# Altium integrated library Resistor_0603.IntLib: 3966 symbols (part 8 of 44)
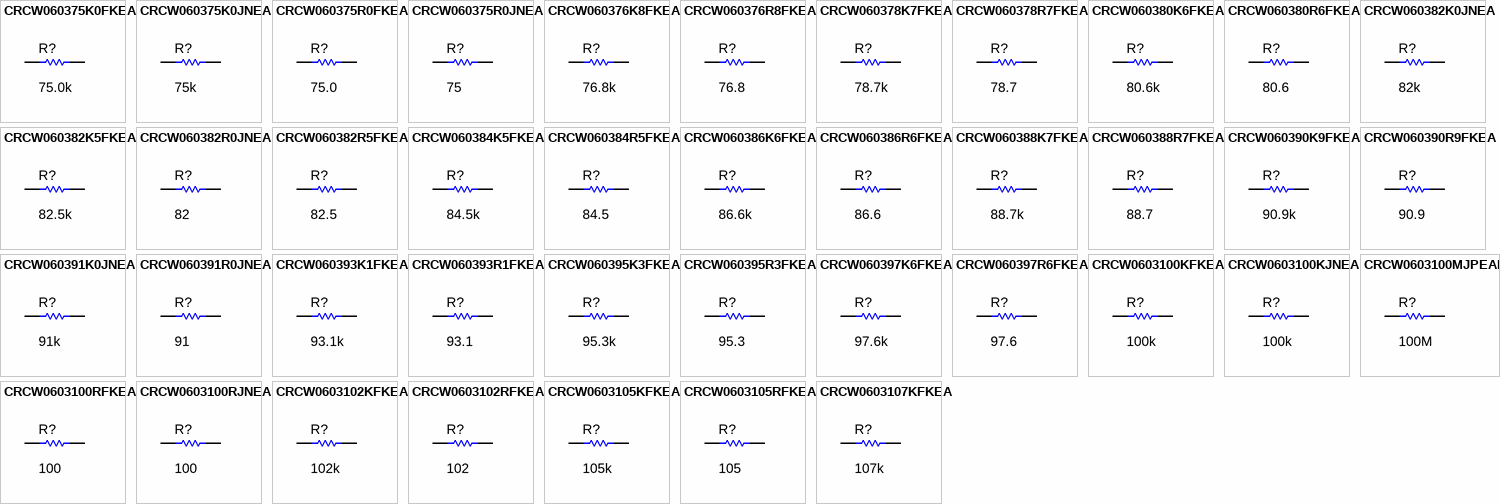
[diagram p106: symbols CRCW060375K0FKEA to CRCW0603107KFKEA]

## CRCW060395R3FKEA
designator R?  ValueDisplayed: 95.3  (hidden comment: CRCW060395R3FKEA)
RES, 95.3, 1%, 0.1 W, 0603; Manufacturer: Vishay-Dale; CompType: Resistor; Value: 95.3; Value_Code: 95R3; Tolerance_%: 1; Power_W: 0.1; Value2: 0.1W; VDC_V: 75; TempCo: 100 ppm/C; SizeArea_mm2: 1.28; SizeX_mm: 1.6; SizeY_mm: 0.8; EIA_Code: E96; U/M: EA; AEC Category: Q200
signal-integrity model Resistor
simulation model Resistor
footprint 0603
footprint 0603M
footprint 0603L
footprint 0603_HV
footprint 0603S
pins: 1, 2

## CRCW060397K6FKEA
designator R?  ValueDisplayed: 97.6k  (hidden comment: CRCW060397K6FKEA)
RES, 97.6 k, 1%, 0.1 W, 0603; Manufacturer: Vishay-Dale; CompType: Resistor; Value: 97.6k; Res_ohm: 97600; Value_Code: 97k6; Tolerance_%: 1; Power_W: 0.1; Value2: 0.1W; VDC_V: 75; TempCo: 100 ppm/C; SizeArea_mm2: 1.28; SizeX_mm: 1.6; SizeY_mm: 0.8; EIA_Code: E96; U/M: EA; AEC Category: Q200; Green_Lifecycle: Active; Green_REACh: Passed
signal-integrity model Resistor
simulation model Resistor
footprint 0603
footprint 0603M
footprint 0603L
footprint 0603_HV
footprint 0603S
pins: 1, 2

## CRCW060397R6FKEA
designator R?  ValueDisplayed: 97.6  (hidden comment: CRCW060397R6FKEA)
RES, 97.6, 1%, 0.1 W, 0603; Manufacturer: Vishay-Dale; CompType: Resistor; Value: 97.6; Value_Code: 97R6; Tolerance_%: 1; Power_W: 0.1; Value2: 0.1W; VDC_V: 75; TempCo: 100 ppm/C; SizeArea_mm2: 1.28; SizeX_mm: 1.6; SizeY_mm: 0.8; EIA_Code: E96; U/M: EA; AEC Category: Q200
signal-integrity model Resistor
simulation model Resistor
footprint 0603
footprint 0603M
footprint 0603L
footprint 0603_HV
footprint 0603S
pins: 1, 2

## CRCW0603100KFKEA
designator R?  ValueDisplayed: 100k  (hidden comment: CRCW0603100KFKEA)
RES, 100 k, 1%, 0.1 W, 0603; Manufacturer: Vishay-Dale; CompType: Resistor; Value: 100k; Res_ohm: 100000; Tolerance_%: 1; Power_W: 0.1; Value2: 0.1W; VDC_V: 75; TempCo: 100 ppm/C; SizeArea_mm2: 1.28; SizeX_mm: 1.6; SizeY_mm: 0.8; EIA_Code: E96; U/M: EA; AEC Category: Q200; Green_Lifecycle: Active; Green_REACh: Passed
signal-integrity model Resistor
simulation model Resistor
footprint 0603
footprint 0603M
footprint 0603L
footprint 0603_HV
footprint 0603S
pins: 1, 2

## CRCW0603100KJNEA
designator R?  ValueDisplayed: 100k  (hidden comment: CRCW0603100KJNEA)
RES, 100 k, 5%, 0.1 W, 0603; Manufacturer: Vishay-Dale; CompType: Resistor; Value: 100k; Res_ohm: 100000; Tolerance_%: 5; Power_W: 0.1; Value2: 0.1W; VDC_V: 75; TempCo: 200 ppm/C; SizeArea_mm2: 1.28; SizeX_mm: 1.6; SizeY_mm: 0.8; SizeZ_mm: 1; EIA_Code: E24; U/M: EA; AEC Category: Q200; Green_Lifecycle: Active; Green_REACh: Passed
signal-integrity model Resistor
simulation model Resistor
footprint 0603
footprint 0603M
footprint 0603L
footprint 0603_HV
footprint 0603S
pins: 1, 2

## CRCW0603100MJPEAHR
designator R?  ValueDisplayed: 100M  (hidden comment: CRCW0603100MJPEAHR)
RES, 100 M, 5%, 0.1 W, 0603; Manufacturer: Vishay-Dale; CompType: Resistor; Value: 100Meg; Res_ohm: 100000000; Tolerance_%: 5; Power_W: 0.1; Value2: 0.1W; VDC_V: 75; TempCo: 500 ppm/C; SizeArea_mm2: 1.28; SizeX_mm: 1.6; SizeY_mm: 0.8; SizeZ_mm: 1; U/M: EA; AEC Category: Q200
signal-integrity model Resistor
simulation model Resistor
footprint 0603
footprint 0603M
footprint 0603L
footprint 0603_HV
footprint 0603S
pins: 1, 2

## CRCW0603100RFKEA
designator R?  ValueDisplayed: 100  (hidden comment: CRCW0603100RFKEA)
RES, 100, 1%, 0.1 W, 0603; Manufacturer: Vishay-Dale; CompType: Resistor; Value: 100; Value_Code: 100R; Tolerance_%: 1; Power_W: 0.1; Value2: 0.1W; VDC_V: 75; TempCo: 100 ppm/C; SizeArea_mm2: 1.28; SizeX_mm: 1.6; SizeY_mm: 0.8; EIA_Code: E96; U/M: EA; AEC Category: Q200; Green_Lifecycle: Active; Green_REACh: Passed
signal-integrity model Resistor
simulation model Resistor
footprint 0603
footprint 0603M
footprint 0603L
footprint 0603_HV
footprint 0603S
pins: 1, 2

## CRCW0603100RJNEA
designator R?  ValueDisplayed: 100  (hidden comment: CRCW0603100RJNEA)
RES, 100, 5%, 0.1 W, 0603; Manufacturer: Vishay-Dale; CompType: Resistor; Value: 100; Value_Code: 100R; Tolerance_%: 5; Power_W: 0.1; Value2: 0.1W; VDC_V: 75; TempCo: 200 ppm/C; SizeArea_mm2: 1.28; SizeX_mm: 1.6; SizeY_mm: 0.8; SizeZ_mm: 1; EIA_Code: E24; U/M: EA; AEC Category: Q200; Green_Lifecycle: Active; Green_REACh: Passed
signal-integrity model Resistor
simulation model Resistor
footprint 0603
footprint 0603M
footprint 0603L
footprint 0603_HV
footprint 0603S
pins: 1, 2

## CRCW0603102KFKEA
designator R?  ValueDisplayed: 102k  (hidden comment: CRCW0603102KFKEA)
RES, 102 k, 1%, 0.1 W, 0603; Manufacturer: Vishay-Dale; CompType: Resistor; Value: 102k; Res_ohm: 102000; Tolerance_%: 1; Power_W: 0.1; Value2: 0.1W; VDC_V: 75; TempCo: 100 ppm/C; SizeArea_mm2: 1.28; SizeX_mm: 1.6; SizeY_mm: 0.8; EIA_Code: E96; U/M: EA; AEC Category: Q200; Green_Lifecycle: Active; Green_REACh: Passed
signal-integrity model Resistor
simulation model Resistor
footprint 0603
footprint 0603M
footprint 0603L
footprint 0603_HV
footprint 0603S
pins: 1, 2

## CRCW0603102RFKEA
designator R?  ValueDisplayed: 102  (hidden comment: CRCW0603102RFKEA)
RES, 102, 1%, 0.1 W, 0603; Manufacturer: Vishay-Dale; CompType: Resistor; Value: 102; Value_Code: 102R; Tolerance_%: 1; Power_W: 0.1; Value2: 0.1W; VDC_V: 75; TempCo: 100 ppm/C; SizeArea_mm2: 1.28; SizeX_mm: 1.6; SizeY_mm: 0.8; EIA_Code: E96; U/M: EA; AEC Category: Q200
signal-integrity model Resistor
simulation model Resistor
footprint 0603
footprint 0603M
footprint 0603L
footprint 0603_HV
footprint 0603S
pins: 1, 2

## CRCW0603105KFKEA
designator R?  ValueDisplayed: 105k  (hidden comment: CRCW0603105KFKEA)
RES, 105 k, 1%, 0.1 W, 0603; Manufacturer: Vishay-Dale; CompType: Resistor; Value: 105k; Res_ohm: 105000; Tolerance_%: 1; Power_W: 0.1; Value2: 0.1W; VDC_V: 75; TempCo: 100 ppm/C; SizeArea_mm2: 1.28; SizeX_mm: 1.6; SizeY_mm: 0.8; EIA_Code: E96; U/M: EA; AEC Category: Q200; Green_Lifecycle: Active; Green_REACh: Passed
signal-integrity model Resistor
simulation model Resistor
footprint 0603
footprint 0603M
footprint 0603L
footprint 0603_HV
footprint 0603S
pins: 1, 2

## CRCW0603105RFKEA
designator R?  ValueDisplayed: 105  (hidden comment: CRCW0603105RFKEA)
RES, 105, 1%, 0.1 W, 0603; Manufacturer: Vishay-Dale; CompType: Resistor; Value: 105; Value_Code: 105R; Tolerance_%: 1; Power_W: 0.1; Value2: 0.1W; VDC_V: 75; TempCo: 100 ppm/C; SizeArea_mm2: 1.28; SizeX_mm: 1.6; SizeY_mm: 0.8; EIA_Code: E96; U/M: EA; AEC Category: Q200
signal-integrity model Resistor
simulation model Resistor
footprint 0603
footprint 0603M
footprint 0603L
footprint 0603_HV
footprint 0603S
pins: 1, 2

## CRCW0603107KFKEA
designator R?  ValueDisplayed: 107k  (hidden comment: CRCW0603107KFKEA)
RES, 107 k, 1%, 0.1 W, 0603; Manufacturer: Vishay-Dale; CompType: Resistor; Value: 107k; Res_ohm: 107000; Tolerance_%: 1; Power_W: 0.1; Value2: 0.1W; VDC_V: 75; TempCo: 100 ppm/C; SizeArea_mm2: 1.28; SizeX_mm: 1.6; SizeY_mm: 0.8; EIA_Code: E96; U/M: EA; AEC Category: Q200
signal-integrity model Resistor
simulation model Resistor
footprint 0603
footprint 0603M
footprint 0603L
footprint 0603_HV
footprint 0603S
pins: 1, 2

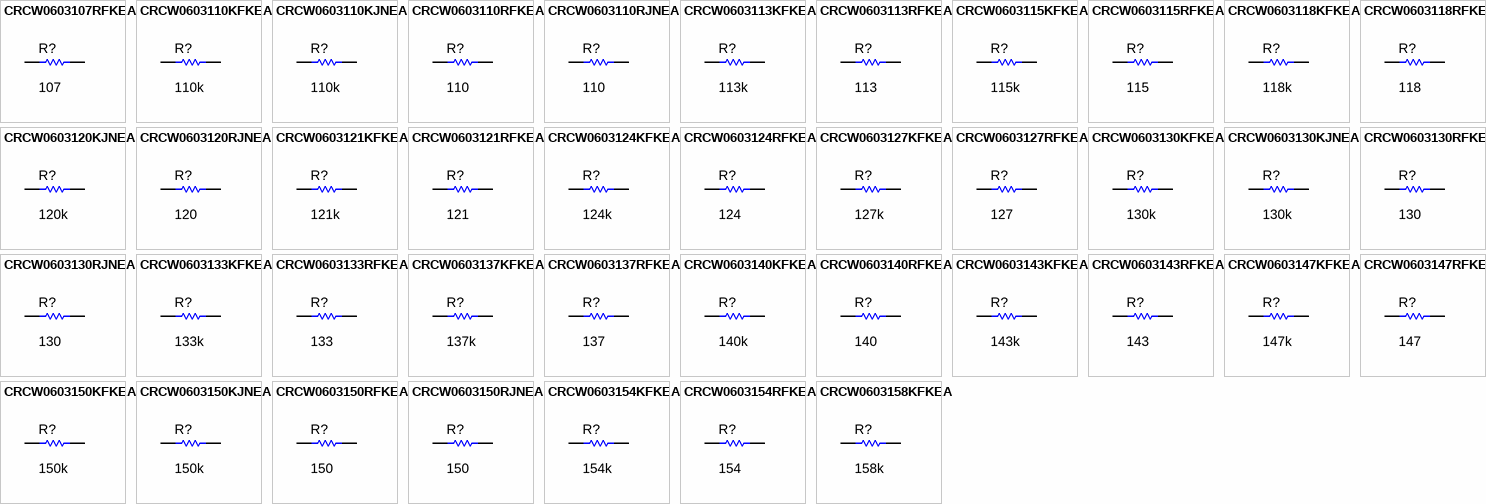
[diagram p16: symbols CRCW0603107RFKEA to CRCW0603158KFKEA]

## CRCW0603107RFKEA
designator R?  ValueDisplayed: 107  (hidden comment: CRCW0603107RFKEA)
RES, 107, 1%, 0.1 W, 0603; Manufacturer: Vishay-Dale; CompType: Resistor; Value: 107; Value_Code: 107R; Tolerance_%: 1; Power_W: 0.1; Value2: 0.1W; VDC_V: 75; TempCo: 100 ppm/C; SizeArea_mm2: 1.28; SizeX_mm: 1.6; SizeY_mm: 0.8; EIA_Code: E96; U/M: EA; AEC Category: Q200
signal-integrity model Resistor
simulation model Resistor
footprint 0603
footprint 0603M
footprint 0603L
footprint 0603_HV
footprint 0603S
pins: 1, 2

## CRCW0603110KFKEA
designator R?  ValueDisplayed: 110k  (hidden comment: CRCW0603110KFKEA)
RES, 110 k, 1%, 0.1 W, 0603; Manufacturer: Vishay-Dale; CompType: Resistor; Value: 110k; Res_ohm: 110000; Tolerance_%: 1; Power_W: 0.1; Value2: 0.1W; VDC_V: 75; TempCo: 100 ppm/C; SizeArea_mm2: 1.28; SizeX_mm: 1.6; SizeY_mm: 0.8; EIA_Code: E96; U/M: EA; AEC Category: Q200; Green_Lifecycle: Active; Green_REACh: Passed
signal-integrity model Resistor
simulation model Resistor
footprint 0603
footprint 0603M
footprint 0603L
footprint 0603_HV
footprint 0603S
pins: 1, 2

## CRCW0603110KJNEA
designator R?  ValueDisplayed: 110k  (hidden comment: CRCW0603110KJNEA)
RES, 110 k, 5%, 0.1 W, 0603; Manufacturer: Vishay-Dale; CompType: Resistor; Value: 110k; Res_ohm: 110000; Tolerance_%: 5; Power_W: 0.1; Value2: 0.1W; VDC_V: 75; TempCo: 200 ppm/C; SizeArea_mm2: 1.28; SizeX_mm: 1.6; SizeY_mm: 0.8; SizeZ_mm: 1; EIA_Code: E24; U/M: EA; AEC Category: Q200
signal-integrity model Resistor
simulation model Resistor
footprint 0603
footprint 0603M
footprint 0603L
footprint 0603_HV
footprint 0603S
pins: 1, 2

## CRCW0603110RFKEA
designator R?  ValueDisplayed: 110  (hidden comment: CRCW0603110RFKEA)
RES, 110, 1%, 0.1 W, 0603; Manufacturer: Vishay-Dale; CompType: Resistor; Value: 110; Value_Code: 110R; Tolerance_%: 1; Power_W: 0.1; Value2: 0.1W; VDC_V: 75; TempCo: 100 ppm/C; SizeArea_mm2: 1.28; SizeX_mm: 1.6; SizeY_mm: 0.8; EIA_Code: E96; U/M: EA; AEC Category: Q200
signal-integrity model Resistor
simulation model Resistor
footprint 0603
footprint 0603M
footprint 0603L
footprint 0603_HV
footprint 0603S
pins: 1, 2

## CRCW0603110RJNEA
designator R?  ValueDisplayed: 110  (hidden comment: CRCW0603110RJNEA)
RES, 110, 5%, 0.1 W, 0603; Manufacturer: Vishay-Dale; CompType: Resistor; Value: 110; Value_Code: 110R; Tolerance_%: 5; Power_W: 0.1; Value2: 0.1W; VDC_V: 75; TempCo: 200 ppm/C; SizeArea_mm2: 1.28; SizeX_mm: 1.6; SizeY_mm: 0.8; SizeZ_mm: 1; EIA_Code: E24; U/M: EA; AEC Category: Q200
signal-integrity model Resistor
simulation model Resistor
footprint 0603
footprint 0603M
footprint 0603L
footprint 0603_HV
footprint 0603S
pins: 1, 2

## CRCW0603113KFKEA
designator R?  ValueDisplayed: 113k  (hidden comment: CRCW0603113KFKEA)
RES, 113 k, 1%, 0.1 W, 0603; Manufacturer: Vishay-Dale; CompType: Resistor; Value: 113k; Res_ohm: 113000; Tolerance_%: 1; Power_W: 0.1; Value2: 0.1W; VDC_V: 75; TempCo: 100 ppm/C; SizeArea_mm2: 1.28; SizeX_mm: 1.6; SizeY_mm: 0.8; EIA_Code: E96; U/M: EA; AEC Category: Q200; Green_Lifecycle: Active; Green_REACh: Passed
signal-integrity model Resistor
simulation model Resistor
footprint 0603
footprint 0603M
footprint 0603L
footprint 0603_HV
footprint 0603S
pins: 1, 2

## CRCW0603113RFKEA
designator R?  ValueDisplayed: 113  (hidden comment: CRCW0603113RFKEA)
RES, 113, 1%, 0.1 W, 0603; Manufacturer: Vishay-Dale; CompType: Resistor; Value: 113; Value_Code: 113R; Tolerance_%: 1; Power_W: 0.1; Value2: 0.1W; VDC_V: 75; TempCo: 100 ppm/C; SizeArea_mm2: 1.28; SizeX_mm: 1.6; SizeY_mm: 0.8; EIA_Code: E96; U/M: EA; AEC Category: Q200; Green_Lifecycle: Active; Green_REACh: Passed
signal-integrity model Resistor
simulation model Resistor
footprint 0603
footprint 0603M
footprint 0603L
footprint 0603_HV
footprint 0603S
pins: 1, 2

## CRCW0603115KFKEA
designator R?  ValueDisplayed: 115k  (hidden comment: CRCW0603115KFKEA)
RES, 115 k, 1%, 0.1 W, 0603; Manufacturer: Vishay-Dale; CompType: Resistor; Value: 115k; Res_ohm: 115000; Tolerance_%: 1; Power_W: 0.1; Value2: 0.1W; VDC_V: 75; TempCo: 100 ppm/C; SizeArea_mm2: 1.28; SizeX_mm: 1.6; SizeY_mm: 0.8; EIA_Code: E96; U/M: EA; AEC Category: Q200; Green_Lifecycle: Active; Green_REACh: Passed
signal-integrity model Resistor
simulation model Resistor
footprint 0603
footprint 0603M
footprint 0603L
footprint 0603_HV
footprint 0603S
pins: 1, 2

## CRCW0603115RFKEA
designator R?  ValueDisplayed: 115  (hidden comment: CRCW0603115RFKEA)
RES, 115, 1%, 0.1 W, 0603; Manufacturer: Vishay-Dale; CompType: Resistor; Value: 115; Value_Code: 115R; Tolerance_%: 1; Power_W: 0.1; Value2: 0.1W; VDC_V: 75; TempCo: 100 ppm/C; SizeArea_mm2: 1.28; SizeX_mm: 1.6; SizeY_mm: 0.8; EIA_Code: E96; U/M: EA; AEC Category: Q200
signal-integrity model Resistor
simulation model Resistor
footprint 0603
footprint 0603M
footprint 0603L
footprint 0603_HV
footprint 0603S
pins: 1, 2

## CRCW0603118KFKEA
designator R?  ValueDisplayed: 118k  (hidden comment: CRCW0603118KFKEA)
RES, 118 k, 1%, 0.1 W, 0603; Manufacturer: Vishay-Dale; CompType: Resistor; Value: 118k; Res_ohm: 118000; Tolerance_%: 1; Power_W: 0.1; Value2: 0.1W; VDC_V: 75; TempCo: 100 ppm/C; SizeArea_mm2: 1.28; SizeX_mm: 1.6; SizeY_mm: 0.8; EIA_Code: E96; U/M: EA; AEC Category: Q200; Green_Lifecycle: Active; Green_REACh: Passed
signal-integrity model Resistor
simulation model Resistor
footprint 0603
footprint 0603M
footprint 0603L
footprint 0603_HV
footprint 0603S
pins: 1, 2

## CRCW0603118RFKEA
designator R?  ValueDisplayed: 118  (hidden comment: CRCW0603118RFKEA)
RES, 118, 1%, 0.1 W, 0603; Manufacturer: Vishay-Dale; CompType: Resistor; Value: 118; Value_Code: 118R; Tolerance_%: 1; Power_W: 0.1; Value2: 0.1W; VDC_V: 75; TempCo: 100 ppm/C; SizeArea_mm2: 1.28; SizeX_mm: 1.6; SizeY_mm: 0.8; EIA_Code: E96; U/M: EA; AEC Category: Q200
signal-integrity model Resistor
simulation model Resistor
footprint 0603
footprint 0603M
footprint 0603L
footprint 0603_HV
footprint 0603S
pins: 1, 2

## CRCW0603120KJNEA
designator R?  ValueDisplayed: 120k  (hidden comment: CRCW0603120KJNEA)
RES, 120 k, 5%, 0.1 W, 0603; Manufacturer: Vishay-Dale; CompType: Resistor; Value: 120k; Res_ohm: 120000; Tolerance_%: 5; Power_W: 0.1; Value2: 0.1W; VDC_V: 75; TempCo: 200 ppm/C; SizeArea_mm2: 1.28; SizeX_mm: 1.6; SizeY_mm: 0.8; SizeZ_mm: 1; EIA_Code: E24; U/M: EA; AEC Category: Q200
signal-integrity model Resistor
simulation model Resistor
footprint 0603
footprint 0603M
footprint 0603L
footprint 0603_HV
footprint 0603S
pins: 1, 2

## CRCW0603120RJNEA
designator R?  ValueDisplayed: 120  (hidden comment: CRCW0603120RJNEA)
RES, 120, 5%, 0.1 W, 0603; Manufacturer: Vishay-Dale; CompType: Resistor; Value: 120; Value_Code: 120R; Tolerance_%: 5; Power_W: 0.1; Value2: 0.1W; VDC_V: 75; TempCo: 200 ppm/C; SizeArea_mm2: 1.28; SizeX_mm: 1.6; SizeY_mm: 0.8; SizeZ_mm: 1; EIA_Code: E24; U/M: EA; AEC Category: Q200; Green_Lifecycle: Active; Green_REACh: Passed
signal-integrity model Resistor
simulation model Resistor
footprint 0603
footprint 0603M
footprint 0603L
footprint 0603_HV
footprint 0603S
pins: 1, 2

## CRCW0603121KFKEA
designator R?  ValueDisplayed: 121k  (hidden comment: CRCW0603121KFKEA)
RES, 121 k, 1%, 0.1 W, 0603; Manufacturer: Vishay-Dale; CompType: Resistor; Value: 121k; Res_ohm: 121000; Tolerance_%: 1; Power_W: 0.1; Value2: 0.1W; VDC_V: 75; TempCo: 100 ppm/C; SizeArea_mm2: 1.28; SizeX_mm: 1.6; SizeY_mm: 0.8; EIA_Code: E96; U/M: EA; AEC Category: Q200; Green_Lifecycle: Active; Green_REACh: Passed
signal-integrity model Resistor
simulation model Resistor
footprint 0603
footprint 0603M
footprint 0603L
footprint 0603_HV
footprint 0603S
pins: 1, 2

## CRCW0603121RFKEA
designator R?  ValueDisplayed: 121  (hidden comment: CRCW0603121RFKEA)
RES, 121, 1%, 0.1 W, 0603; Manufacturer: Vishay-Dale; CompType: Resistor; Value: 121; Value_Code: 121R; Tolerance_%: 1; Power_W: 0.1; Value2: 0.1W; VDC_V: 75; TempCo: 100 ppm/C; SizeArea_mm2: 1.28; SizeX_mm: 1.6; SizeY_mm: 0.8; EIA_Code: E96; U/M: EA; AEC Category: Q200
signal-integrity model Resistor
simulation model Resistor
footprint 0603
footprint 0603M
footprint 0603L
footprint 0603_HV
footprint 0603S
pins: 1, 2

## CRCW0603124KFKEA
designator R?  ValueDisplayed: 124k  (hidden comment: CRCW0603124KFKEA)
RES, 124 k, 1%, 0.1 W, 0603; Manufacturer: Vishay-Dale; CompType: Resistor; Value: 124k; Res_ohm: 124000; Tolerance_%: 1; Power_W: 0.1; Value2: 0.1W; VDC_V: 75; TempCo: 100 ppm/C; SizeArea_mm2: 1.28; SizeX_mm: 1.6; SizeY_mm: 0.8; EIA_Code: E96; U/M: EA; AEC Category: Q200; Green_Lifecycle: Active; Green_REACh: Passed
signal-integrity model Resistor
simulation model Resistor
footprint 0603
footprint 0603M
footprint 0603L
footprint 0603_HV
footprint 0603S
pins: 1, 2

## CRCW0603124RFKEA
designator R?  ValueDisplayed: 124  (hidden comment: CRCW0603124RFKEA)
RES, 124, 1%, 0.1 W, 0603; Manufacturer: Vishay-Dale; CompType: Resistor; Value: 124; Value_Code: 124R; Tolerance_%: 1; Power_W: 0.1; Value2: 0.1W; VDC_V: 75; TempCo: 100 ppm/C; SizeArea_mm2: 1.28; SizeX_mm: 1.6; SizeY_mm: 0.8; EIA_Code: E96; U/M: EA; AEC Category: Q200
signal-integrity model Resistor
simulation model Resistor
footprint 0603
footprint 0603M
footprint 0603L
footprint 0603_HV
footprint 0603S
pins: 1, 2

## CRCW0603127KFKEA
designator R?  ValueDisplayed: 127k  (hidden comment: CRCW0603127KFKEA)
RES, 127 k, 1%, 0.1 W, 0603; Manufacturer: Vishay-Dale; CompType: Resistor; Value: 127k; Res_ohm: 127000; Tolerance_%: 1; Power_W: 0.1; Value2: 0.1W; VDC_V: 75; TempCo: 100 ppm/C; SizeArea_mm2: 1.28; SizeX_mm: 1.6; SizeY_mm: 0.8; EIA_Code: E96; U/M: EA; AEC Category: Q200; Green_Lifecycle: Active; Green_REACh: Passed
signal-integrity model Resistor
simulation model Resistor
footprint 0603
footprint 0603M
footprint 0603L
footprint 0603_HV
footprint 0603S
pins: 1, 2

## CRCW0603127RFKEA
designator R?  ValueDisplayed: 127  (hidden comment: CRCW0603127RFKEA)
RES, 127, 1%, 0.1 W, 0603; Manufacturer: Vishay-Dale; CompType: Resistor; Value: 127; Value_Code: 127R; Tolerance_%: 1; Power_W: 0.1; Value2: 0.1W; VDC_V: 75; TempCo: 100 ppm/C; SizeArea_mm2: 1.28; SizeX_mm: 1.6; SizeY_mm: 0.8; EIA_Code: E96; U/M: EA; AEC Category: Q200
signal-integrity model Resistor
simulation model Resistor
footprint 0603
footprint 0603M
footprint 0603L
footprint 0603_HV
footprint 0603S
pins: 1, 2

## CRCW0603130KFKEA
designator R?  ValueDisplayed: 130k  (hidden comment: CRCW0603130KFKEA)
RES, 130 k, 1%, 0.1 W, 0603; Manufacturer: Vishay-Dale; CompType: Resistor; Value: 130k; Res_ohm: 130000; Tolerance_%: 1; Power_W: 0.1; Value2: 0.1W; VDC_V: 75; TempCo: 100 ppm/C; SizeArea_mm2: 1.28; SizeX_mm: 1.6; SizeY_mm: 0.8; EIA_Code: E96; U/M: EA; AEC Category: Q200; Green_Lifecycle: Active; Green_REACh: Passed
signal-integrity model Resistor
simulation model Resistor
footprint 0603
footprint 0603M
footprint 0603L
footprint 0603_HV
footprint 0603S
pins: 1, 2

## CRCW0603130KJNEA
designator R?  ValueDisplayed: 130k  (hidden comment: CRCW0603130KJNEA)
RES, 130 k, 5%, 0.1 W, 0603; Manufacturer: Vishay-Dale; CompType: Resistor; Value: 130k; Res_ohm: 130000; Tolerance_%: 5; Power_W: 0.1; Value2: 0.1W; VDC_V: 75; TempCo: 200 ppm/C; SizeArea_mm2: 1.28; SizeX_mm: 1.6; SizeY_mm: 0.8; SizeZ_mm: 1; EIA_Code: E24; U/M: EA; AEC Category: Q200; Green_Lifecycle: Active; Green_REACh: Passed
signal-integrity model Resistor
simulation model Resistor
footprint 0603
footprint 0603M
footprint 0603L
footprint 0603_HV
footprint 0603S
pins: 1, 2

## CRCW0603130RFKEA
designator R?  ValueDisplayed: 130  (hidden comment: CRCW0603130RFKEA)
RES, 130, 1%, 0.1 W, 0603; Manufacturer: Vishay-Dale; CompType: Resistor; Value: 130; Value_Code: 130R; Tolerance_%: 1; Power_W: 0.1; Value2: 0.1W; VDC_V: 75; TempCo: 100 ppm/C; SizeArea_mm2: 1.28; SizeX_mm: 1.6; SizeY_mm: 0.8; EIA_Code: E96; U/M: EA; AEC Category: Q200
signal-integrity model Resistor
simulation model Resistor
footprint 0603
footprint 0603M
footprint 0603L
footprint 0603_HV
footprint 0603S
pins: 1, 2

## CRCW0603130RJNEA
designator R?  ValueDisplayed: 130  (hidden comment: CRCW0603130RJNEA)
RES, 130, 5%, 0.1 W, 0603; Manufacturer: Vishay-Dale; CompType: Resistor; Value: 130; Value_Code: 130R; Tolerance_%: 5; Power_W: 0.1; Value2: 0.1W; VDC_V: 75; TempCo: 200 ppm/C; SizeArea_mm2: 1.28; SizeX_mm: 1.6; SizeY_mm: 0.8; SizeZ_mm: 1; EIA_Code: E24; U/M: EA; AEC Category: Q200
signal-integrity model Resistor
simulation model Resistor
footprint 0603
footprint 0603M
footprint 0603L
footprint 0603_HV
footprint 0603S
pins: 1, 2

## CRCW0603133KFKEA
designator R?  ValueDisplayed: 133k  (hidden comment: CRCW0603133KFKEA)
RES, 133 k, 1%, 0.1 W, 0603; Manufacturer: Vishay-Dale; CompType: Resistor; Value: 133k; Res_ohm: 133000; Tolerance_%: 1; Power_W: 0.1; Value2: 0.1W; VDC_V: 75; TempCo: 100 ppm/C; SizeArea_mm2: 1.28; SizeX_mm: 1.6; SizeY_mm: 0.8; EIA_Code: E96; U/M: EA; AEC Category: Q200; Green_Lifecycle: Active; Green_REACh: Passed
signal-integrity model Resistor
simulation model Resistor
footprint 0603
footprint 0603M
footprint 0603L
footprint 0603_HV
footprint 0603S
pins: 1, 2

## CRCW0603133RFKEA
designator R?  ValueDisplayed: 133  (hidden comment: CRCW0603133RFKEA)
RES, 133, 1%, 0.1 W, 0603; Manufacturer: Vishay-Dale; CompType: Resistor; Value: 133; Value_Code: 133R; Tolerance_%: 1; Power_W: 0.1; Value2: 0.1W; VDC_V: 75; TempCo: 100 ppm/C; SizeArea_mm2: 1.28; SizeX_mm: 1.6; SizeY_mm: 0.8; EIA_Code: E96; U/M: EA; AEC Category: Q200
signal-integrity model Resistor
simulation model Resistor
footprint 0603
footprint 0603M
footprint 0603L
footprint 0603_HV
footprint 0603S
pins: 1, 2

## CRCW0603137KFKEA
designator R?  ValueDisplayed: 137k  (hidden comment: CRCW0603137KFKEA)
RES, 137 k, 1%, 0.1 W, 0603; Manufacturer: Vishay-Dale; CompType: Resistor; Value: 137k; Res_ohm: 137000; Tolerance_%: 1; Power_W: 0.1; Value2: 0.1W; VDC_V: 75; TempCo: 100 ppm/C; SizeArea_mm2: 1.28; SizeX_mm: 1.6; SizeY_mm: 0.8; EIA_Code: E96; U/M: EA; AEC Category: Q200; Green_Lifecycle: Active; Green_REACh: Passed
signal-integrity model Resistor
simulation model Resistor
footprint 0603
footprint 0603M
footprint 0603L
footprint 0603_HV
footprint 0603S
pins: 1, 2

## CRCW0603137RFKEA
designator R?  ValueDisplayed: 137  (hidden comment: CRCW0603137RFKEA)
RES, 137, 1%, 0.1 W, 0603; Manufacturer: Vishay-Dale; CompType: Resistor; Value: 137; Value_Code: 137R; Tolerance_%: 1; Power_W: 0.1; Value2: 0.1W; VDC_V: 75; TempCo: 100 ppm/C; SizeArea_mm2: 1.28; SizeX_mm: 1.6; SizeY_mm: 0.8; EIA_Code: E96; U/M: EA; AEC Category: Q200; Green_Lifecycle: Active; Green_REACh: Passed
signal-integrity model Resistor
simulation model Resistor
footprint 0603
footprint 0603M
footprint 0603L
footprint 0603_HV
footprint 0603S
pins: 1, 2

## CRCW0603140KFKEA
designator R?  ValueDisplayed: 140k  (hidden comment: CRCW0603140KFKEA)
RES, 140 k, 1%, 0.1 W, 0603; Manufacturer: Vishay-Dale; CompType: Resistor; Value: 140k; Res_ohm: 140000; Tolerance_%: 1; Power_W: 0.1; Value2: 0.1W; VDC_V: 75; TempCo: 100 ppm/C; SizeArea_mm2: 1.28; SizeX_mm: 1.6; SizeY_mm: 0.8; EIA_Code: E96; U/M: EA; AEC Category: Q200; Green_Lifecycle: Active; Green_REACh: Passed
signal-integrity model Resistor
simulation model Resistor
footprint 0603
footprint 0603M
footprint 0603L
footprint 0603_HV
footprint 0603S
pins: 1, 2

## CRCW0603140RFKEA
designator R?  ValueDisplayed: 140  (hidden comment: CRCW0603140RFKEA)
RES, 140, 1%, 0.1 W, 0603; Manufacturer: Vishay-Dale; CompType: Resistor; Value: 140; Value_Code: 140R; Tolerance_%: 1; Power_W: 0.1; Value2: 0.1W; VDC_V: 75; TempCo: 100 ppm/C; SizeArea_mm2: 1.28; SizeX_mm: 1.6; SizeY_mm: 0.8; EIA_Code: E96; U/M: EA; AEC Category: Q200
signal-integrity model Resistor
simulation model Resistor
footprint 0603
footprint 0603M
footprint 0603L
footprint 0603_HV
footprint 0603S
pins: 1, 2

## CRCW0603143KFKEA
designator R?  ValueDisplayed: 143k  (hidden comment: CRCW0603143KFKEA)
RES, 143 k, 1%, 0.1 W, 0603; Manufacturer: Vishay-Dale; CompType: Resistor; Value: 143k; Res_ohm: 143000; Tolerance_%: 1; Power_W: 0.1; Value2: 0.1W; VDC_V: 75; TempCo: 100 ppm/C; SizeArea_mm2: 1.28; SizeX_mm: 1.6; SizeY_mm: 0.8; EIA_Code: E96; U/M: EA; AEC Category: Q200; Green_Lifecycle: Active; Green_REACh: Passed
signal-integrity model Resistor
simulation model Resistor
footprint 0603
footprint 0603M
footprint 0603L
footprint 0603_HV
footprint 0603S
pins: 1, 2

## CRCW0603143RFKEA
designator R?  ValueDisplayed: 143  (hidden comment: CRCW0603143RFKEA)
RES, 143, 1%, 0.1 W, 0603; Manufacturer: Vishay-Dale; CompType: Resistor; Value: 143; Value_Code: 143R; Tolerance_%: 1; Power_W: 0.1; Value2: 0.1W; VDC_V: 75; TempCo: 100 ppm/C; SizeArea_mm2: 1.28; SizeX_mm: 1.6; SizeY_mm: 0.8; EIA_Code: E96; U/M: EA; AEC Category: Q200; Green_Lifecycle: Active; Green_REACh: Passed
signal-integrity model Resistor
simulation model Resistor
footprint 0603
footprint 0603M
footprint 0603L
footprint 0603_HV
footprint 0603S
pins: 1, 2

## CRCW0603147KFKEA
designator R?  ValueDisplayed: 147k  (hidden comment: CRCW0603147KFKEA)
RES, 147 k, 1%, 0.1 W, 0603; Manufacturer: Vishay-Dale; CompType: Resistor; Value: 147k; Res_ohm: 147000; Tolerance_%: 1; Power_W: 0.1; Value2: 0.1W; VDC_V: 75; TempCo: 100 ppm/C; SizeArea_mm2: 1.28; SizeX_mm: 1.6; SizeY_mm: 0.8; EIA_Code: E96; U/M: EA; AEC Category: Q200; Green_Lifecycle: Active; Green_REACh: Passed
signal-integrity model Resistor
simulation model Resistor
footprint 0603
footprint 0603M
footprint 0603L
footprint 0603_HV
footprint 0603S
pins: 1, 2

## CRCW0603147RFKEA
designator R?  ValueDisplayed: 147  (hidden comment: CRCW0603147RFKEA)
RES, 147, 1%, 0.1 W, 0603; Manufacturer: Vishay-Dale; CompType: Resistor; Value: 147; Value_Code: 147R; Tolerance_%: 1; Power_W: 0.1; Value2: 0.1W; VDC_V: 75; TempCo: 100 ppm/C; SizeArea_mm2: 1.28; SizeX_mm: 1.6; SizeY_mm: 0.8; EIA_Code: E96; U/M: EA; AEC Category: Q200
signal-integrity model Resistor
simulation model Resistor
footprint 0603
footprint 0603M
footprint 0603L
footprint 0603_HV
footprint 0603S
pins: 1, 2

## CRCW0603150KFKEA
designator R?  ValueDisplayed: 150k  (hidden comment: CRCW0603150KFKEA)
RES, 150 k, 1%, 0.1 W, 0603; Manufacturer: Vishay-Dale; CompType: Resistor; Value: 150k; Res_ohm: 150000; Tolerance_%: 1; Power_W: 0.1; Value2: 0.1W; VDC_V: 75; TempCo: 100 ppm/C; SizeArea_mm2: 1.28; SizeX_mm: 1.6; SizeY_mm: 0.8; EIA_Code: E96; U/M: EA; AEC Category: Q200; Green_Lifecycle: Active; Green_REACh: Passed
signal-integrity model Resistor
simulation model Resistor
footprint 0603
footprint 0603M
footprint 0603L
footprint 0603_HV
footprint 0603S
pins: 1, 2

## CRCW0603150KJNEA
designator R?  ValueDisplayed: 150k  (hidden comment: CRCW0603150KJNEA)
RES, 150 k, 5%, 0.1 W, 0603; Manufacturer: Vishay-Dale; CompType: Resistor; Value: 150k; Res_ohm: 150000; Tolerance_%: 5; Power_W: 0.1; Value2: 0.1W; VDC_V: 75; TempCo: 200 ppm/C; SizeArea_mm2: 1.28; SizeX_mm: 1.6; SizeY_mm: 0.8; SizeZ_mm: 1; EIA_Code: E24; U/M: EA; AEC Category: Q200
signal-integrity model Resistor
simulation model Resistor
footprint 0603
footprint 0603M
footprint 0603L
footprint 0603_HV
footprint 0603S
pins: 1, 2

## CRCW0603150RFKEA
designator R?  ValueDisplayed: 150  (hidden comment: CRCW0603150RFKEA)
RES, 150, 1%, 0.1 W, 0603; Manufacturer: Vishay-Dale; CompType: Resistor; Value: 150; Value_Code: 150R; Tolerance_%: 1; Power_W: 0.1; Value2: 0.1W; VDC_V: 75; TempCo: 100 ppm/C; SizeArea_mm2: 1.28; SizeX_mm: 1.6; SizeY_mm: 0.8; EIA_Code: E96; U/M: EA; AEC Category: Q200; Green_Lifecycle: Active; Green_REACh: Passed
signal-integrity model Resistor
simulation model Resistor
footprint 0603
footprint 0603M
footprint 0603L
footprint 0603_HV
footprint 0603S
pins: 1, 2

## CRCW0603150RJNEA
designator R?  ValueDisplayed: 150  (hidden comment: CRCW0603150RJNEA)
RES, 150, 5%, 0.1 W, 0603; Manufacturer: Vishay-Dale; CompType: Resistor; Value: 150; Value_Code: 150R; Tolerance_%: 5; Power_W: 0.1; Value2: 0.1W; VDC_V: 75; TempCo: 200 ppm/C; SizeArea_mm2: 1.28; SizeX_mm: 1.6; SizeY_mm: 0.8; SizeZ_mm: 1; EIA_Code: E24; U/M: EA; AEC Category: Q200; Green_Lifecycle: Active; Green_REACh: Passed
signal-integrity model Resistor
simulation model Resistor
footprint 0603
footprint 0603M
footprint 0603L
footprint 0603_HV
footprint 0603S
pins: 1, 2

## CRCW0603154KFKEA
designator R?  ValueDisplayed: 154k  (hidden comment: CRCW0603154KFKEA)
RES, 154 k, 1%, 0.1 W, 0603; Manufacturer: Vishay-Dale; CompType: Resistor; Value: 154k; Res_ohm: 154000; Tolerance_%: 1; Power_W: 0.1; Value2: 0.1W; VDC_V: 75; TempCo: 100 ppm/C; SizeArea_mm2: 1.28; SizeX_mm: 1.6; SizeY_mm: 0.8; EIA_Code: E96; U/M: EA; AEC Category: Q200; Green_Lifecycle: Active; Green_REACh: Passed
signal-integrity model Resistor
simulation model Resistor
footprint 0603
footprint 0603M
footprint 0603L
footprint 0603_HV
footprint 0603S
pins: 1, 2

## CRCW0603154RFKEA
designator R?  ValueDisplayed: 154  (hidden comment: CRCW0603154RFKEA)
RES, 154, 1%, 0.1 W, 0603; Manufacturer: Vishay-Dale; CompType: Resistor; Value: 154; Value_Code: 154R; Tolerance_%: 1; Power_W: 0.1; Value2: 0.1W; VDC_V: 75; TempCo: 100 ppm/C; SizeArea_mm2: 1.28; SizeX_mm: 1.6; SizeY_mm: 0.8; EIA_Code: E96; U/M: EA; AEC Category: Q200
signal-integrity model Resistor
simulation model Resistor
footprint 0603
footprint 0603M
footprint 0603L
footprint 0603_HV
footprint 0603S
pins: 1, 2

## CRCW0603158KFKEA
designator R?  ValueDisplayed: 158k  (hidden comment: CRCW0603158KFKEA)
RES, 158 k, 1%, 0.1 W, 0603; Manufacturer: Vishay-Dale; CompType: Resistor; Value: 158k; Res_ohm: 158000; Tolerance_%: 1; Power_W: 0.1; Value2: 0.1W; VDC_V: 75; TempCo: 100 ppm/C; SizeArea_mm2: 1.28; SizeX_mm: 1.6; SizeY_mm: 0.8; EIA_Code: E96; U/M: EA; AEC Category: Q200; Green_Lifecycle: Active; Green_REACh: Passed
signal-integrity model Resistor
simulation model Resistor
footprint 0603
footprint 0603M
footprint 0603L
footprint 0603_HV
footprint 0603S
pins: 1, 2

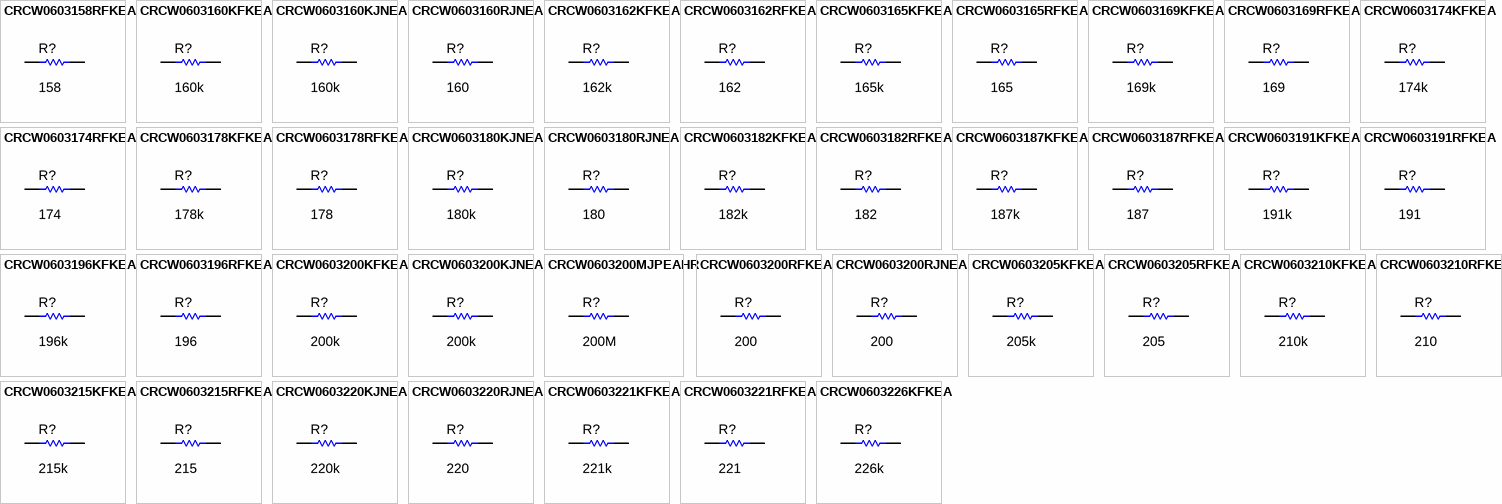
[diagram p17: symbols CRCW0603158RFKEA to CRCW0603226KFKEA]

## CRCW0603158RFKEA
designator R?  ValueDisplayed: 158  (hidden comment: CRCW0603158RFKEA)
RES, 158, 1%, 0.1 W, 0603; Manufacturer: Vishay-Dale; CompType: Resistor; Value: 158; Value_Code: 158R; Tolerance_%: 1; Power_W: 0.1; Value2: 0.1W; VDC_V: 75; TempCo: 100 ppm/C; SizeArea_mm2: 1.28; SizeX_mm: 1.6; SizeY_mm: 0.8; EIA_Code: E96; U/M: EA; AEC Category: Q200
signal-integrity model Resistor
simulation model Resistor
footprint 0603
footprint 0603M
footprint 0603L
footprint 0603_HV
footprint 0603S
pins: 1, 2

## CRCW0603160KFKEA
designator R?  ValueDisplayed: 160k  (hidden comment: CRCW0603160KFKEA)
RES, 160 k, 1%, 0.1 W, 0603; Manufacturer: Vishay-Dale; CompType: Resistor; Value: 160k; Res_ohm: 160000; Tolerance_%: 1; Power_W: 0.1; Value2: 0.1W; VDC_V: 75; TempCo: 100 ppm/C; SizeArea_mm2: 1.28; SizeX_mm: 1.6; SizeY_mm: 0.8; U/M: EA; AEC Category: Q200; Green_Lifecycle: Active; Green_REACh: Passed
signal-integrity model Resistor
simulation model Resistor
footprint 0603
footprint 0603M
footprint 0603L
footprint 0603_HV
footprint 0603S
pins: 1, 2

## CRCW0603160KJNEA
designator R?  ValueDisplayed: 160k  (hidden comment: CRCW0603160KJNEA)
RES, 160 k, 5%, 0.1 W, 0603; Manufacturer: Vishay-Dale; CompType: Resistor; Value: 160k; Res_ohm: 160000; Tolerance_%: 5; Power_W: 0.1; Value2: 0.1W; VDC_V: 75; TempCo: 200 ppm/C; SizeArea_mm2: 1.28; SizeX_mm: 1.6; SizeY_mm: 0.8; SizeZ_mm: 1; EIA_Code: E24; U/M: EA; AEC Category: Q200
signal-integrity model Resistor
simulation model Resistor
footprint 0603
footprint 0603M
footprint 0603L
footprint 0603_HV
footprint 0603S
pins: 1, 2

## CRCW0603160RJNEA
designator R?  ValueDisplayed: 160  (hidden comment: CRCW0603160RJNEA)
RES, 160, 5%, 0.1 W, 0603; Manufacturer: Vishay-Dale; CompType: Resistor; Value: 160; Value_Code: 160R; Tolerance_%: 5; Power_W: 0.1; Value2: 0.1W; VDC_V: 75; TempCo: 200 ppm/C; SizeArea_mm2: 1.28; SizeX_mm: 1.6; SizeY_mm: 0.8; SizeZ_mm: 1; EIA_Code: E24; U/M: EA; AEC Category: Q200
signal-integrity model Resistor
simulation model Resistor
footprint 0603
footprint 0603M
footprint 0603L
footprint 0603_HV
footprint 0603S
pins: 1, 2

## CRCW0603162KFKEA
designator R?  ValueDisplayed: 162k  (hidden comment: CRCW0603162KFKEA)
RES, 162 k, 1%, 0.1 W, 0603; Manufacturer: Vishay-Dale; CompType: Resistor; Value: 162k; Res_ohm: 162000; Tolerance_%: 1; Power_W: 0.1; Value2: 0.1W; VDC_V: 75; TempCo: 100 ppm/C; SizeArea_mm2: 1.28; SizeX_mm: 1.6; SizeY_mm: 0.8; EIA_Code: E96; U/M: EA; AEC Category: Q200; Green_Lifecycle: Active; Green_REACh: Passed
signal-integrity model Resistor
simulation model Resistor
footprint 0603
footprint 0603M
footprint 0603L
footprint 0603_HV
footprint 0603S
pins: 1, 2

## CRCW0603162RFKEA
designator R?  ValueDisplayed: 162  (hidden comment: CRCW0603162RFKEA)
RES, 162, 1%, 0.1 W, 0603; Manufacturer: Vishay-Dale; CompType: Resistor; Value: 162; Value_Code: 162R; Tolerance_%: 1; Power_W: 0.1; Value2: 0.1W; VDC_V: 75; TempCo: 100 ppm/C; SizeArea_mm2: 1.28; SizeX_mm: 1.6; SizeY_mm: 0.8; EIA_Code: E96; U/M: EA; AEC Category: Q200; Green_Lifecycle: Active; Green_REACh: Passed
signal-integrity model Resistor
simulation model Resistor
footprint 0603
footprint 0603M
footprint 0603L
footprint 0603_HV
footprint 0603S
pins: 1, 2

## CRCW0603165KFKEA
designator R?  ValueDisplayed: 165k  (hidden comment: CRCW0603165KFKEA)
RES, 165 k, 1%, 0.1 W, 0603; Manufacturer: Vishay-Dale; CompType: Resistor; Value: 165k; Res_ohm: 165000; Tolerance_%: 1; Power_W: 0.1; Value2: 0.1W; VDC_V: 75; TempCo: 100 ppm/C; SizeArea_mm2: 1.28; SizeX_mm: 1.6; SizeY_mm: 0.8; EIA_Code: E96; U/M: EA; AEC Category: Q200; Green_Lifecycle: Active; Green_REACh: Passed
signal-integrity model Resistor
simulation model Resistor
footprint 0603
footprint 0603M
footprint 0603L
footprint 0603_HV
footprint 0603S
pins: 1, 2

## CRCW0603165RFKEA
designator R?  ValueDisplayed: 165  (hidden comment: CRCW0603165RFKEA)
RES, 165, 1%, 0.1 W, 0603; Manufacturer: Vishay-Dale; CompType: Resistor; Value: 165; Value_Code: 165R; Tolerance_%: 1; Power_W: 0.1; Value2: 0.1W; VDC_V: 75; TempCo: 100 ppm/C; SizeArea_mm2: 1.28; SizeX_mm: 1.6; SizeY_mm: 0.8; EIA_Code: E96; U/M: EA; AEC Category: Q200
signal-integrity model Resistor
simulation model Resistor
footprint 0603
footprint 0603M
footprint 0603L
footprint 0603_HV
footprint 0603S
pins: 1, 2

## CRCW0603169KFKEA
designator R?  ValueDisplayed: 169k  (hidden comment: CRCW0603169KFKEA)
RES, 169 k, 1%, 0.1 W, 0603; Manufacturer: Vishay-Dale; CompType: Resistor; Value: 169k; Res_ohm: 169000; Tolerance_%: 1; Power_W: 0.1; Value2: 0.1W; VDC_V: 75; TempCo: 100 ppm/C; SizeArea_mm2: 1.28; SizeX_mm: 1.6; SizeY_mm: 0.8; EIA_Code: E96; U/M: EA; AEC Category: Q200; Green_Lifecycle: Active; Green_REACh: Passed
signal-integrity model Resistor
simulation model Resistor
footprint 0603
footprint 0603M
footprint 0603L
footprint 0603_HV
footprint 0603S
pins: 1, 2

## CRCW0603169RFKEA
designator R?  ValueDisplayed: 169  (hidden comment: CRCW0603169RFKEA)
RES, 169, 1%, 0.1 W, 0603; Manufacturer: Vishay-Dale; CompType: Resistor; Value: 169; Value_Code: 169R; Tolerance_%: 1; Power_W: 0.1; Value2: 0.1W; VDC_V: 75; TempCo: 100 ppm/C; SizeArea_mm2: 1.28; SizeX_mm: 1.6; SizeY_mm: 0.8; EIA_Code: E96; U/M: EA; AEC Category: Q200; Green_Lifecycle: Active; Green_REACh: Passed
signal-integrity model Resistor
simulation model Resistor
footprint 0603
footprint 0603M
footprint 0603L
footprint 0603_HV
footprint 0603S
pins: 1, 2

## CRCW0603174KFKEA
designator R?  ValueDisplayed: 174k  (hidden comment: CRCW0603174KFKEA)
RES, 174 k, 1%, 0.1 W, 0603; Manufacturer: Vishay-Dale; CompType: Resistor; Value: 174k; Res_ohm: 174000; Tolerance_%: 1; Power_W: 0.1; Value2: 0.1W; VDC_V: 75; TempCo: 100 ppm/C; SizeArea_mm2: 1.28; SizeX_mm: 1.6; SizeY_mm: 0.8; EIA_Code: E96; U/M: EA; AEC Category: Q200; Green_Lifecycle: Active; Green_REACh: Passed
signal-integrity model Resistor
simulation model Resistor
footprint 0603
footprint 0603M
footprint 0603L
footprint 0603_HV
footprint 0603S
pins: 1, 2

## CRCW0603174RFKEA
designator R?  ValueDisplayed: 174  (hidden comment: CRCW0603174RFKEA)
RES, 174, 1%, 0.1 W, 0603; Manufacturer: Vishay-Dale; CompType: Resistor; Value: 174; Value_Code: 174R; Tolerance_%: 1; Power_W: 0.1; Value2: 0.1W; VDC_V: 75; TempCo: 100 ppm/C; SizeArea_mm2: 1.28; SizeX_mm: 1.6; SizeY_mm: 0.8; EIA_Code: E96; U/M: EA; AEC Category: Q200
signal-integrity model Resistor
simulation model Resistor
footprint 0603
footprint 0603M
footprint 0603L
footprint 0603_HV
footprint 0603S
pins: 1, 2

## CRCW0603178KFKEA
designator R?  ValueDisplayed: 178k  (hidden comment: CRCW0603178KFKEA)
RES, 178 k, 1%, 0.1 W, 0603; Manufacturer: Vishay-Dale; CompType: Resistor; Value: 178k; Res_ohm: 178000; Tolerance_%: 1; Power_W: 0.1; Value2: 0.1W; VDC_V: 75; TempCo: 100 ppm/C; SizeArea_mm2: 1.28; SizeX_mm: 1.6; SizeY_mm: 0.8; EIA_Code: E96; U/M: EA; AEC Category: Q200; Green_Lifecycle: Active; Green_REACh: Passed
signal-integrity model Resistor
simulation model Resistor
footprint 0603
footprint 0603M
footprint 0603L
footprint 0603_HV
footprint 0603S
pins: 1, 2

## CRCW0603178RFKEA
designator R?  ValueDisplayed: 178  (hidden comment: CRCW0603178RFKEA)
RES, 178, 1%, 0.1 W, 0603; Manufacturer: Vishay-Dale; CompType: Resistor; Value: 178; Value_Code: 178R; Tolerance_%: 1; Power_W: 0.1; Value2: 0.1W; VDC_V: 75; TempCo: 100 ppm/C; SizeArea_mm2: 1.28; SizeX_mm: 1.6; SizeY_mm: 0.8; EIA_Code: E96; U/M: EA; AEC Category: Q200
signal-integrity model Resistor
simulation model Resistor
footprint 0603
footprint 0603M
footprint 0603L
footprint 0603_HV
footprint 0603S
pins: 1, 2

## CRCW0603180KJNEA
designator R?  ValueDisplayed: 180k  (hidden comment: CRCW0603180KJNEA)
RES, 180 k, 5%, 0.1 W, 0603; Manufacturer: Vishay-Dale; CompType: Resistor; Value: 180k; Res_ohm: 180000; Tolerance_%: 5; Power_W: 0.1; Value2: 0.1W; VDC_V: 75; TempCo: 200 ppm/C; SizeArea_mm2: 1.28; SizeX_mm: 1.6; SizeY_mm: 0.8; SizeZ_mm: 1; EIA_Code: E24; U/M: EA; AEC Category: Q200
signal-integrity model Resistor
simulation model Resistor
footprint 0603
footprint 0603M
footprint 0603L
footprint 0603_HV
footprint 0603S
pins: 1, 2

## CRCW0603180RJNEA
designator R?  ValueDisplayed: 180  (hidden comment: CRCW0603180RJNEA)
RES, 180, 5%, 0.1 W, 0603; Manufacturer: Vishay-Dale; CompType: Resistor; Value: 180; Value_Code: 180R; Tolerance_%: 5; Power_W: 0.1; Value2: 0.1W; VDC_V: 75; TempCo: 200 ppm/C; SizeArea_mm2: 1.28; SizeX_mm: 1.6; SizeY_mm: 0.8; SizeZ_mm: 1; EIA_Code: E24; U/M: EA; AEC Category: Q200; Green_Lifecycle: Active; Green_REACh: Passed
signal-integrity model Resistor
simulation model Resistor
footprint 0603
footprint 0603M
footprint 0603L
footprint 0603_HV
footprint 0603S
pins: 1, 2

## CRCW0603182KFKEA
designator R?  ValueDisplayed: 182k  (hidden comment: CRCW0603182KFKEA)
RES, 182 k, 1%, 0.1 W, 0603; Manufacturer: Vishay-Dale; CompType: Resistor; Value: 182k; Res_ohm: 182000; Tolerance_%: 1; Power_W: 0.1; Value2: 0.1W; VDC_V: 75; TempCo: 100 ppm/C; SizeArea_mm2: 1.28; SizeX_mm: 1.6; SizeY_mm: 0.8; EIA_Code: E96; U/M: EA; AEC Category: Q200; Green_Lifecycle: Active; Green_REACh: Passed
signal-integrity model Resistor
simulation model Resistor
footprint 0603
footprint 0603M
footprint 0603L
footprint 0603_HV
footprint 0603S
pins: 1, 2

## CRCW0603182RFKEA
designator R?  ValueDisplayed: 182  (hidden comment: CRCW0603182RFKEA)
RES, 182, 1%, 0.1 W, 0603; Manufacturer: Vishay-Dale; CompType: Resistor; Value: 182; Value_Code: 182R; Tolerance_%: 1; Power_W: 0.1; Value2: 0.1W; VDC_V: 75; TempCo: 100 ppm/C; SizeArea_mm2: 1.28; SizeX_mm: 1.6; SizeY_mm: 0.8; EIA_Code: E96; U/M: EA; AEC Category: Q200
signal-integrity model Resistor
simulation model Resistor
footprint 0603
footprint 0603M
footprint 0603L
footprint 0603_HV
footprint 0603S
pins: 1, 2

## CRCW0603187KFKEA
designator R?  ValueDisplayed: 187k  (hidden comment: CRCW0603187KFKEA)
RES, 187 k, 1%, 0.1 W, 0603; Manufacturer: Vishay-Dale; CompType: Resistor; Value: 187k; Res_ohm: 187000; Tolerance_%: 1; Power_W: 0.1; Value2: 0.1W; VDC_V: 75; TempCo: 100 ppm/C; SizeArea_mm2: 1.28; SizeX_mm: 1.6; SizeY_mm: 0.8; EIA_Code: E96; U/M: EA; AEC Category: Q200; Green_Lifecycle: Active; Green_REACh: Passed
signal-integrity model Resistor
simulation model Resistor
footprint 0603
footprint 0603M
footprint 0603L
footprint 0603_HV
footprint 0603S
pins: 1, 2

## CRCW0603187RFKEA
designator R?  ValueDisplayed: 187  (hidden comment: CRCW0603187RFKEA)
RES, 187, 1%, 0.1 W, 0603; Manufacturer: Vishay-Dale; CompType: Resistor; Value: 187; Value_Code: 187R; Tolerance_%: 1; Power_W: 0.1; Value2: 0.1W; VDC_V: 75; TempCo: 100 ppm/C; SizeArea_mm2: 1.28; SizeX_mm: 1.6; SizeY_mm: 0.8; EIA_Code: E96; U/M: EA; AEC Category: Q200
signal-integrity model Resistor
simulation model Resistor
footprint 0603
footprint 0603M
footprint 0603L
footprint 0603_HV
footprint 0603S
pins: 1, 2

## CRCW0603191KFKEA
designator R?  ValueDisplayed: 191k  (hidden comment: CRCW0603191KFKEA)
RES, 191 k, 1%, 0.1 W, 0603; Manufacturer: Vishay-Dale; CompType: Resistor; Value: 191k; Res_ohm: 191000; Tolerance_%: 1; Power_W: 0.1; Value2: 0.1W; VDC_V: 75; TempCo: 100 ppm/C; SizeArea_mm2: 1.28; SizeX_mm: 1.6; SizeY_mm: 0.8; EIA_Code: E96; U/M: EA; AEC Category: Q200; Green_Lifecycle: Active; Green_REACh: Passed
signal-integrity model Resistor
simulation model Resistor
footprint 0603
footprint 0603M
footprint 0603L
footprint 0603_HV
footprint 0603S
pins: 1, 2

## CRCW0603191RFKEA
designator R?  ValueDisplayed: 191  (hidden comment: CRCW0603191RFKEA)
RES, 191, 1%, 0.1 W, 0603; Manufacturer: Vishay-Dale; CompType: Resistor; Value: 191; Value_Code: 191R; Tolerance_%: 1; Power_W: 0.1; Value2: 0.1W; VDC_V: 75; TempCo: 100 ppm/C; SizeArea_mm2: 1.28; SizeX_mm: 1.6; SizeY_mm: 0.8; EIA_Code: E96; U/M: EA; AEC Category: Q200; Green_Lifecycle: Active; Green_REACh: Passed
signal-integrity model Resistor
simulation model Resistor
footprint 0603
footprint 0603M
footprint 0603L
footprint 0603_HV
footprint 0603S
pins: 1, 2

## CRCW0603196KFKEA
designator R?  ValueDisplayed: 196k  (hidden comment: CRCW0603196KFKEA)
RES, 196 k, 1%, 0.1 W, 0603; Manufacturer: Vishay-Dale; CompType: Resistor; Value: 196k; Res_ohm: 196000; Tolerance_%: 1; Power_W: 0.1; Value2: 0.1W; VDC_V: 75; TempCo: 100 ppm/C; SizeArea_mm2: 1.28; SizeX_mm: 1.6; SizeY_mm: 0.8; EIA_Code: E96; U/M: EA; AEC Category: Q200; Green_Lifecycle: Active; Green_REACh: Passed
signal-integrity model Resistor
simulation model Resistor
footprint 0603
footprint 0603M
footprint 0603L
footprint 0603_HV
footprint 0603S
pins: 1, 2

## CRCW0603196RFKEA
designator R?  ValueDisplayed: 196  (hidden comment: CRCW0603196RFKEA)
RES, 196, 1%, 0.1 W, 0603; Manufacturer: Vishay-Dale; CompType: Resistor; Value: 196; Value_Code: 196R; Tolerance_%: 1; Power_W: 0.1; Value2: 0.1W; VDC_V: 75; TempCo: 100 ppm/C; SizeArea_mm2: 1.28; SizeX_mm: 1.6; SizeY_mm: 0.8; EIA_Code: E96; U/M: EA; AEC Category: Q200
signal-integrity model Resistor
simulation model Resistor
footprint 0603
footprint 0603M
footprint 0603L
footprint 0603_HV
footprint 0603S
pins: 1, 2

## CRCW0603200KFKEA
designator R?  ValueDisplayed: 200k  (hidden comment: CRCW0603200KFKEA)
RES, 200 k, 1%, 0.1 W, 0603; Manufacturer: Vishay-Dale; CompType: Resistor; Value: 200k; Res_ohm: 200000; Tolerance_%: 1; Power_W: 0.1; Value2: 0.1W; VDC_V: 75; TempCo: 100 ppm/C; SizeArea_mm2: 1.28; SizeX_mm: 1.6; SizeY_mm: 0.8; EIA_Code: E96; U/M: EA; AEC Category: Q200; Green_Lifecycle: Active; Green_REACh: Passed
signal-integrity model Resistor
simulation model Resistor
footprint 0603
footprint 0603M
footprint 0603L
footprint 0603_HV
footprint 0603S
pins: 1, 2

## CRCW0603200KJNEA
designator R?  ValueDisplayed: 200k  (hidden comment: CRCW0603200KJNEA)
RES, 200 k, 5%, 0.1 W, 0603; Manufacturer: Vishay-Dale; CompType: Resistor; Value: 200k; Res_ohm: 200000; Tolerance_%: 5; Power_W: 0.1; Value2: 0.1W; VDC_V: 75; TempCo: 200 ppm/C; SizeArea_mm2: 1.28; SizeX_mm: 1.6; SizeY_mm: 0.8; SizeZ_mm: 1; EIA_Code: E24; U/M: EA; AEC Category: Q200; Green_Lifecycle: Active; Green_REACh: Passed
signal-integrity model Resistor
simulation model Resistor
footprint 0603
footprint 0603M
footprint 0603L
footprint 0603_HV
footprint 0603S
pins: 1, 2

## CRCW0603200MJPEAHR
designator R?  ValueDisplayed: 200M  (hidden comment: CRCW0603200MJPEAHR)
RES, 200 M, 5%, 0.1 W, 0603; Manufacturer: Vishay-Dale; CompType: Resistor; Value: 200Meg; Res_ohm: 200000000; Tolerance_%: 5; Power_W: 0.1; Value2: 0.1W; VDC_V: 75; TempCo: 500 ppm/C; SizeArea_mm2: 1.3175; SizeX_mm: 1.55; SizeY_mm: 0.85; SizeZ_mm: 0.5; U/M: EA; AEC Category: Q200; AEC Qualified: N
signal-integrity model Resistor
simulation model Resistor
footprint 0603_HR
pins: 1, 2

## CRCW0603200RFKEA
designator R?  ValueDisplayed: 200  (hidden comment: CRCW0603200RFKEA)
RES, 200, 1%, 0.1 W, 0603; Manufacturer: Vishay-Dale; CompType: Resistor; Value: 200; Value_Code: 200R; Tolerance_%: 1; Power_W: 0.1; Value2: 0.1W; VDC_V: 75; TempCo: 100 ppm/C; SizeArea_mm2: 1.28; SizeX_mm: 1.6; SizeY_mm: 0.8; EIA_Code: E96; U/M: EA; AEC Category: Q200; Green_Lifecycle: Active; Green_REACh: Passed
signal-integrity model Resistor
simulation model Resistor
footprint 0603
footprint 0603M
footprint 0603L
footprint 0603_HV
footprint 0603S
pins: 1, 2

## CRCW0603200RJNEA
designator R?  ValueDisplayed: 200  (hidden comment: CRCW0603200RJNEA)
RES, 200, 5%, 0.1 W, 0603; Manufacturer: Vishay-Dale; CompType: Resistor; Value: 200; Value_Code: 200R; Tolerance_%: 5; Power_W: 0.1; Value2: 0.1W; VDC_V: 75; TempCo: 200 ppm/C; SizeArea_mm2: 1.28; SizeX_mm: 1.6; SizeY_mm: 0.8; SizeZ_mm: 1; EIA_Code: E24; U/M: EA; AEC Category: Q200; Green_Lifecycle: Active; Green_REACh: Passed
signal-integrity model Resistor
simulation model Resistor
footprint 0603
footprint 0603M
footprint 0603L
footprint 0603_HV
footprint 0603S
pins: 1, 2

## CRCW0603205KFKEA
designator R?  ValueDisplayed: 205k  (hidden comment: CRCW0603205KFKEA)
RES, 205 k, 1%, 0.1 W, 0603; Manufacturer: Vishay-Dale; CompType: Resistor; Value: 205k; Res_ohm: 205000; Tolerance_%: 1; Power_W: 0.1; Value2: 0.1W; VDC_V: 75; TempCo: 100 ppm/C; SizeArea_mm2: 1.28; SizeX_mm: 1.6; SizeY_mm: 0.8; EIA_Code: E96; U/M: EA; AEC Category: Q200; Green_Lifecycle: Active; Green_REACh: Passed
signal-integrity model Resistor
simulation model Resistor
footprint 0603
footprint 0603M
footprint 0603L
footprint 0603_HV
footprint 0603S
pins: 1, 2

## CRCW0603205RFKEA
designator R?  ValueDisplayed: 205  (hidden comment: CRCW0603205RFKEA)
RES, 205, 1%, 0.1 W, 0603; Manufacturer: Vishay-Dale; CompType: Resistor; Value: 205; Value_Code: 205R; Tolerance_%: 1; Power_W: 0.1; Value2: 0.1W; VDC_V: 75; TempCo: 100 ppm/C; SizeArea_mm2: 1.28; SizeX_mm: 1.6; SizeY_mm: 0.8; EIA_Code: E96; U/M: EA; AEC Category: Q200
signal-integrity model Resistor
simulation model Resistor
footprint 0603
footprint 0603M
footprint 0603L
footprint 0603_HV
footprint 0603S
pins: 1, 2

## CRCW0603210KFKEA
designator R?  ValueDisplayed: 210k  (hidden comment: CRCW0603210KFKEA)
RES, 210 k, 1%, 0.1 W, 0603; Manufacturer: Vishay-Dale; CompType: Resistor; Value: 210k; Res_ohm: 210000; Tolerance_%: 1; Power_W: 0.1; Value2: 0.1W; VDC_V: 75; TempCo: 100 ppm/C; SizeArea_mm2: 1.28; SizeX_mm: 1.6; SizeY_mm: 0.8; EIA_Code: E96; U/M: EA; AEC Category: Q200; Green_Lifecycle: Active; Green_REACh: Passed
signal-integrity model Resistor
simulation model Resistor
footprint 0603
footprint 0603M
footprint 0603L
footprint 0603_HV
footprint 0603S
pins: 1, 2

## CRCW0603210RFKEA
designator R?  ValueDisplayed: 210  (hidden comment: CRCW0603210RFKEA)
RES, 210, 1%, 0.1 W, 0603; Manufacturer: Vishay-Dale; CompType: Resistor; Value: 210; Value_Code: 210R; Tolerance_%: 1; Power_W: 0.1; Value2: 0.1W; VDC_V: 75; TempCo: 100 ppm/C; SizeArea_mm2: 1.28; SizeX_mm: 1.6; SizeY_mm: 0.8; EIA_Code: E96; U/M: EA; AEC Category: Q200
signal-integrity model Resistor
simulation model Resistor
footprint 0603
footprint 0603M
footprint 0603L
footprint 0603_HV
footprint 0603S
pins: 1, 2

## CRCW0603215KFKEA
designator R?  ValueDisplayed: 215k  (hidden comment: CRCW0603215KFKEA)
RES, 215 k, 1%, 0.1 W, 0603; Manufacturer: Vishay-Dale; CompType: Resistor; Value: 215k; Res_ohm: 215000; Tolerance_%: 1; Power_W: 0.1; Value2: 0.1W; VDC_V: 75; TempCo: 100 ppm/C; SizeArea_mm2: 1.28; SizeX_mm: 1.6; SizeY_mm: 0.8; EIA_Code: E96; U/M: EA; AEC Category: Q200
signal-integrity model Resistor
simulation model Resistor
footprint 0603
footprint 0603M
footprint 0603L
footprint 0603_HV
footprint 0603S
pins: 1, 2

## CRCW0603215RFKEA
designator R?  ValueDisplayed: 215  (hidden comment: CRCW0603215RFKEA)
RES, 215, 1%, 0.1 W, 0603; Manufacturer: Vishay-Dale; CompType: Resistor; Value: 215; Value_Code: 215R; Tolerance_%: 1; Power_W: 0.1; Value2: 0.1W; VDC_V: 75; TempCo: 100 ppm/C; SizeArea_mm2: 1.28; SizeX_mm: 1.6; SizeY_mm: 0.8; EIA_Code: E96; U/M: EA; AEC Category: Q200
signal-integrity model Resistor
simulation model Resistor
footprint 0603
footprint 0603M
footprint 0603L
footprint 0603_HV
footprint 0603S
pins: 1, 2

## CRCW0603220KJNEA
designator R?  ValueDisplayed: 220k  (hidden comment: CRCW0603220KJNEA)
RES, 220 k, 5%, 0.1 W, 0603; Manufacturer: Vishay-Dale; CompType: Resistor; Value: 220k; Res_ohm: 220000; Tolerance_%: 5; Power_W: 0.1; Value2: 0.1W; VDC_V: 75; TempCo: 200 ppm/C; SizeArea_mm2: 1.28; SizeX_mm: 1.6; SizeY_mm: 0.8; SizeZ_mm: 1; EIA_Code: E24; U/M: EA; AEC Category: Q200
signal-integrity model Resistor
simulation model Resistor
footprint 0603
footprint 0603M
footprint 0603L
footprint 0603_HV
footprint 0603S
pins: 1, 2

## CRCW0603220RJNEA
designator R?  ValueDisplayed: 220  (hidden comment: CRCW0603220RJNEA)
RES, 220, 5%, 0.1 W, 0603; Manufacturer: Vishay-Dale; CompType: Resistor; Value: 220; Value_Code: 220R; Tolerance_%: 5; Power_W: 0.1; Value2: 0.1W; VDC_V: 75; TempCo: 200 ppm/C; SizeArea_mm2: 1.28; SizeX_mm: 1.6; SizeY_mm: 0.8; SizeZ_mm: 1; EIA_Code: E24; U/M: EA; AEC Category: Q200; Green_Lifecycle: Active; Green_REACh: Passed
signal-integrity model Resistor
simulation model Resistor
footprint 0603
footprint 0603M
footprint 0603L
footprint 0603_HV
footprint 0603S
pins: 1, 2

## CRCW0603221KFKEA
designator R?  ValueDisplayed: 221k  (hidden comment: CRCW0603221KFKEA)
RES, 221 k, 1%, 0.1 W, 0603; Manufacturer: Vishay-Dale; CompType: Resistor; Value: 221k; Res_ohm: 221000; Tolerance_%: 1; Power_W: 0.1; Value2: 0.1W; VDC_V: 75; TempCo: 100 ppm/C; SizeArea_mm2: 1.28; SizeX_mm: 1.6; SizeY_mm: 0.8; EIA_Code: E96; U/M: EA; AEC Category: Q200
signal-integrity model Resistor
simulation model Resistor
footprint 0603
footprint 0603M
footprint 0603L
footprint 0603_HV
footprint 0603S
pins: 1, 2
